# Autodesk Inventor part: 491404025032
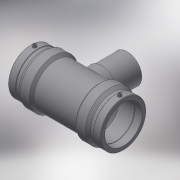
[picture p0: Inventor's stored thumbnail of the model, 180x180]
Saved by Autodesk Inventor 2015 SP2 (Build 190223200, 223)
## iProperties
Created: 2017-06
Part Number: 491404025032
Material: Generic
Description: PLASSON REDUCING TEE 25x32x25
Document SubType Name: Modeling
Designer: KIM
Mass: 119.996 g
Surface Area: 371.42 cm^2
Volume: 119.996 cm^3
Density: 1 g/cm^3
Appearance: Default
Author: KIM
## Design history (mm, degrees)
derived "491404.ipt"
feature "Solid1::491404.ipt"
tag "TaggingFeature1"
body "Solid1"
other parameters: "d0" = 104, "d1" = 25, "d2" = 44, "d3" = 39, "d4" = 20.8, "d5" = 39.6, "d6" = 23.75, "d7" = 25, "d8" = 168 deg, "d10" = 15.6, "d11" = 5.2, "d13" = 104, "d14" = 17.6296, "d17" = 22.5, "d18" = 25, "d19" = 3.52592, "d20" = 168 deg, "d22" = 40.92, "d23" = 44, "d25" = 135 deg, "d26" = 72.8, "d29" = 43, "d30" = 15, "d31" = 41.6, "d34" = 5 deg, "d35" = 15, "d39" = 5 deg, "d41" = 4, "d42" = 14, "d43" = 0, "d45" = 4, "d46" = 6, "d47" = 0, "d48" = -74, "d49" = 32, "d51" = 0, "d52" = 25.6, "d54" = 0, "d55" = 39.6, "d56" = 44, "d57" = 36.4, "d58" = 135 deg, "d59" = 39, "d60" = 39, "d61" = 135 deg, "d62" = 74, "d72" = 47.32, "d73" = 23.66, "d74" = -74, "d75" = 33.6, "d77" = 0, "d78" = 25.6, "d80" = 0, "d81" = 32, "d82" = 52, "d83" = 0, "d84" = 3, "d85" = 0, "d86" = 13, "d87" = 40.1016, "d88" = 5.2, "d89" = 3, "d90" = 0, "d_" = 25, "L_" = 104, "L_1" = 39, "D_" = 44, "A_" = 43, "d_2" = 12, "H_" = 74, "d_1" = 32
